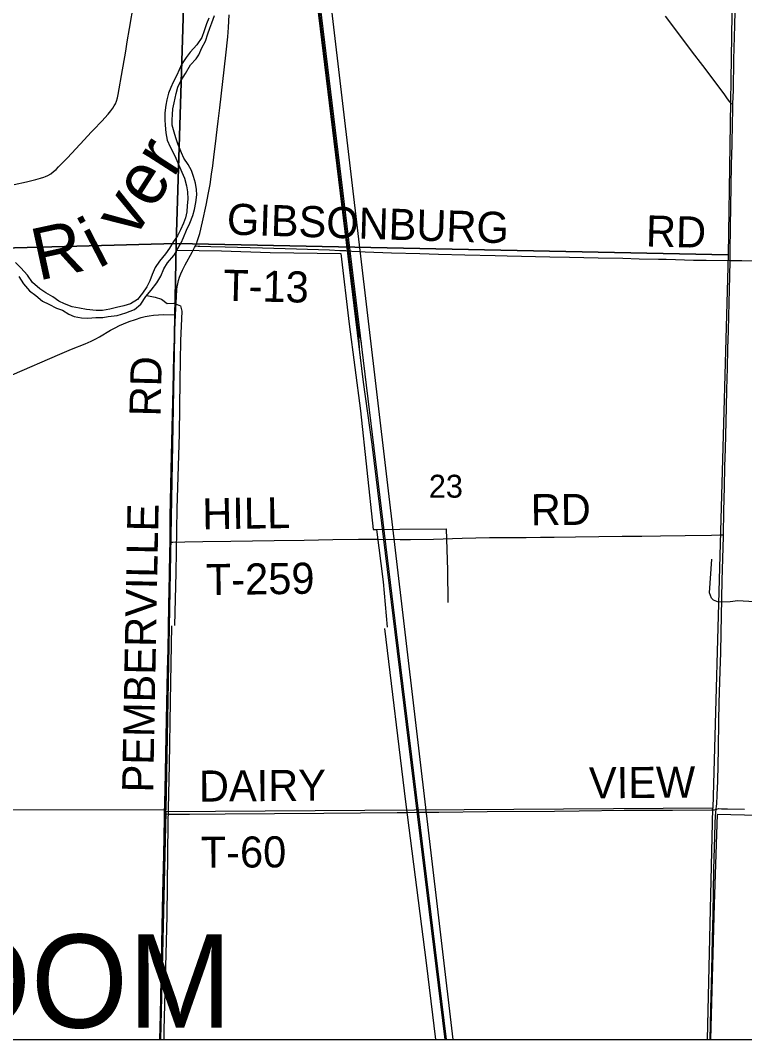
# Model space of a CAD drawing. Extents: x 0 to 34, y 0 to 22.
# Drawn here: x 4.754 to 6.077, y 14.1 to 15.963 of the extents above; entities that cross this region are included whole.
import ezdxf

# ---------------------------------------------------------------- set-up
doc = ezdxf.new("R2010")
doc.units = 0
for name, color, linetype in [('Default', 7, 'Continuous'), ('GM_X_County_Road', 7, 'Continuous'), ('GM_X_County_Road_Text', 7, 'Continuous'), ('GM_X_Major_River', 7, 'Continuous'), ('GM_X_Major_River_Text', 7, 'Continuous'), ('GM_X_Minor_River', 7, 'Continuous'), ('GM_X_Rail_Line', 7, 'Continuous'), ('GM_X_Section', 7, 'Continuous'), ('GM_X_Section_Text', 7, 'Continuous'), ('GM_X_Township_Road', 7, 'Continuous'), ('GM_X_Township_Road_Text', 7, 'Continuous'), ('GM_X_Township_Text', 7, 'Continuous'), ('SH_Cut_Line', 7, 'Continuous'), ('SH_Data', 7, 'Continuous')]:
    doc.layers.add(name, color=color, linetype=linetype)

msp = doc.modelspace()

# ---------------------------------------------------------------- linework, layer by layer
at = {"layer": 'Default'}
for points in [[(4.0075, 14.1), (5.0106, 14.1), (5.0199, 14.516), (5.0199, 14.5201), (4.0206, 14.5179)], [(5.0106, 14.1), (6.0095, 14.1), (6.0193, 14.5231), (5.0199, 14.516)]]:
    msp.add_lwpolyline(points, close=True, dxfattribs=at)
msp.add_lwpolyline([(2.1, 14.1), (7.0155, 14.1)], dxfattribs=at)
at = {"layer": 'GM_X_County_Road'}
for points in [[(4.7429, 15.663), (4.7657, 15.668), (4.7823, 15.6718), (4.7914, 15.6742), (4.7974, 15.6761), (4.8003, 15.6773), (4.8046, 15.6793), (4.81, 15.6826), (4.815, 15.6864), (4.8198, 15.6905), (4.8242, 15.6949), (4.8285, 15.6994), (4.8402, 15.7119), (4.871, 15.7448), (4.8839, 15.7583), (4.8882, 15.7628), (4.9031, 15.7787), (4.9147, 15.7913), (4.9197, 15.7973), (4.9234, 15.8024), (4.9259, 15.8064), (4.928, 15.8106), (4.9298, 15.815), (4.9317, 15.821), (4.9331, 15.8271), (4.9349, 15.8379), (4.939, 15.8624), (4.9468, 15.9068), (4.9497, 15.9237), (4.9539, 15.9482), (4.9617, 15.9942)], [(5.0741, 15.5507), (5.0758, 15.5545), (5.078, 15.5603), (5.0799, 15.5662), (5.0819, 15.5736), (5.0869, 15.5947), (5.0936, 15.6251), (5.0982, 15.6479), (5.101, 15.6632), (5.1038, 15.6816), (5.1059, 15.6969), (5.1085, 15.7185), (5.1108, 15.737), (5.1138, 15.7632), (5.1156, 15.7787), (5.1186, 15.8033), (5.1243, 15.8512), (5.1298, 15.899), (5.1333, 15.933), (5.1346, 15.95), (5.1359, 15.9732)], [(5.038, 15.4248), (5.0396, 15.4581), (5.0404, 15.4705), (5.041, 15.4768), (5.0417, 15.4814), (5.0431, 15.4875), (5.045, 15.4935), (5.0473, 15.4994), (5.0505, 15.5065), (5.0556, 15.5162), (5.0684, 15.5393), (5.0726, 15.5475), (5.0741, 15.5507)], [(5.0277, 15.0091), (5.0283, 15.056), (5.0301, 15.1411), (5.0319, 15.2188), (5.0334, 15.2897), (5.0348, 15.3506), (5.0366, 15.3964), (5.038, 15.4248)], [(5.0176, 14.5124), (5.0186, 14.5562), (5.0208, 14.6538), (5.022, 14.7147), (5.0234, 14.7744), (5.0243, 14.813), (5.0258, 14.8937), (5.0268, 14.9503), (5.0274, 14.9907), (5.0277, 15.0091)], [(5.0092, 14.1), (5.0102, 14.1454), (5.0134, 14.307), (5.0145, 14.3673), (5.0162, 14.4381), (5.0174, 14.5034), (5.0176, 14.5124)]]:
    msp.add_lwpolyline(points, dxfattribs=at)
at = {"layer": 'GM_X_Major_River'}
for points in [[(5.0985, 15.967), (5.0941, 15.9565), (5.09, 15.9437), (5.0859, 15.9313), (5.0765, 15.9182), (5.0648, 15.9045), (5.0573, 15.8948), (5.0487, 15.8825), (5.0443, 15.8723), (5.0399, 15.8626), (5.0335, 15.8502), (5.0291, 15.8401), (5.0251, 15.8299), (5.0221, 15.8178), (5.02, 15.808), (5.0185, 15.794), (5.0185, 15.7811), (5.0191, 15.7716), (5.0202, 15.7572), (5.0225, 15.7442), (5.0283, 15.7319), (5.0333, 15.7216), (5.0384, 15.7108), (5.0491, 15.6854), (5.054, 15.6743), (5.058, 15.6605), (5.0597, 15.6494), (5.0604, 15.6363), (5.059, 15.6245), (5.0583, 15.6132), (5.0561, 15.6022), (5.0525, 15.5924), (5.0469, 15.58), (5.0413, 15.5692), (5.0339, 15.5587), (5.0267, 15.5468), (5.0197, 15.5359), (5.0083, 15.5225), (5.0003, 15.5112), (4.9949, 15.4986), (4.9908, 15.4869), (4.9852, 15.476), (4.9777, 15.4644), (4.9684, 15.4525), (4.9553, 15.4445), (4.9431, 15.441), (4.9298, 15.4379), (4.9179, 15.4348), (4.9046, 15.4328), (4.8929, 15.4323), (4.8751, 15.4343), (4.8623, 15.4369), (4.8491, 15.4391), (4.8347, 15.4446), (4.8249, 15.4497), (4.8138, 15.4576), (4.8009, 15.4646), (4.7898, 15.4721), (4.7768, 15.4837), (4.7672, 15.4969), (4.7551, 15.5104), (4.7455, 15.5205)], [(4.7513, 15.4946), (4.76, 15.4815), (4.7711, 15.4687), (4.7826, 15.4601), (4.7945, 15.4499), (4.8065, 15.4443), (4.8203, 15.4368), (4.8312, 15.4331), (4.8431, 15.4256), (4.8529, 15.4219), (4.866, 15.4193), (4.8778, 15.4187), (4.8922, 15.4195), (4.9047, 15.4199), (4.915, 15.4216), (4.931, 15.4235), (4.947, 15.4284), (4.9626, 15.4346), (4.9746, 15.4444), (4.9836, 15.4579), (4.9934, 15.4698), (5.0036, 15.4832), (5.0111, 15.4955), (5.0167, 15.509), (5.0234, 15.5195), (5.0344, 15.5329), (5.0399, 15.543), (5.0478, 15.5561), (5.0526, 15.5659), (5.0578, 15.5794), (5.0639, 15.5925), (5.0695, 15.6061), (5.0724, 15.6174), (5.075, 15.6298), (5.0765, 15.6442), (5.076, 15.6537), (5.0744, 15.6655), (5.0709, 15.6778), (5.067, 15.6885), (5.0608, 15.6996), (5.0532, 15.7108), (5.0485, 15.7208), (5.0421, 15.7373), (5.0382, 15.7484), (5.035, 15.7583), (5.0319, 15.7713), (5.0314, 15.7812), (5.032, 15.791), (5.033, 15.8009), (5.0352, 15.8122), (5.0387, 15.8292), (5.042, 15.8409), (5.0472, 15.8522), (5.0562, 15.8656), (5.0654, 15.8817), (5.0752, 15.8923), (5.0802, 15.8999), (5.0858, 15.9127), (5.0925, 15.9251), (5.097, 15.9382), (5.1007, 15.9488), (5.104, 15.9586), (5.1092, 15.9717)]]:
    msp.add_lwpolyline(points, dxfattribs=at)
at = {"layer": 'GM_X_Minor_River'}
for points in [[(5.0399, 15.543), (5.122, 15.5414), (5.2106, 15.5389), (5.34, 15.5365), (5.3547, 15.4079), (5.3757, 15.2491), (5.3874, 15.141), (5.3987, 15.0322), (5.4052, 15.0321), (5.4476, 15.0329), (5.5324, 15.0335), (5.5344, 14.958), (5.5352, 14.8987)], [(4.9855, 15.4601), (5.0003, 15.4567), (5.0119, 15.4534), (5.0223, 15.4452), (5.0345, 15.446), (5.0469, 15.441), (5.0496, 15.4316)], [(5.0496, 15.4316), (5.0468, 15.3774), (5.0457, 15.3038), (5.0445, 15.2074), (5.0403, 15.0701), (5.0385, 14.9533), (5.0361, 14.8566)], [(5.4052, 15.0321), (5.4168, 14.9365), (5.4246, 14.8536)], [(6.1645, 14.8956), (6.065, 14.9022), (6.051, 14.9002), (6.0298, 14.8996), (6.0204, 14.9029), (6.0167, 14.9068), (6.0131, 14.9163), (6.0173, 14.9781)], [(5.0302, 14.8562), (5.0281, 14.718), (5.0263, 14.6022), (5.024, 14.4955), (5.0221, 14.3257), (5.0165, 14.1181), (5.0162, 14.1)], [(5.4196, 14.8514), (5.4579, 14.5345), (5.4954, 14.2401), (5.5126, 14.1)], [(6.3168, 14.5272), (6.3166, 14.5075), (6.1764, 14.5075), (6.0272, 14.5114), (6.0217, 14.3475), (6.0152, 14.1)]]:
    msp.add_lwpolyline(points, dxfattribs=at)
at = {"layer": 'GM_X_Rail_Line'}
for p, q in [((5.3745, 15.3541), (5.3721, 15.3935)), ((5.3721, 15.3935), (5.3771, 15.374)), ((5.4556, 14.8553), (5.5444, 14.1))]:
    msp.add_line(p, q, dxfattribs=at)
for points in [[(5.533, 14.1), (5.4414, 14.8452), (5.2368, 16.5291), (5.1973, 16.873), (5.1794, 17.0253), (5.1537, 17.2322), (5.1303, 17.4189), (5.1198, 17.5024), (5.1038, 17.6379), (5.0605, 17.8802), (4.9539, 18.5048), (4.7781, 19.5207), (4.6486, 20.2766), (4.541, 20.9)], [(5.1575, 17.231), (5.1689, 17.2254), (5.1772, 17.2171), (5.4556, 14.8553)], [(5.3972, 15.1881), (5.3809, 15.3015), (5.2318, 16.5285), (5.1928, 16.873), (5.1831, 16.9698)], [(5.3721, 15.3935), (5.372, 15.3954), (5.2343, 16.5288), (5.2026, 16.8071)], [(5.5304, 14.1), (5.4389, 14.8449), (5.3972, 15.1881)]]:
    msp.add_lwpolyline(points, dxfattribs=at)
at = {"layer": 'GM_X_Section'}
for points in [[(4.0656, 16.5335), (5.0695, 16.5364), (5.0389, 15.5548), (4.0396, 15.5284)], [(5.0695, 16.5364), (6.0628, 16.5344), (6.0471, 15.5341), (5.0389, 15.5548)], [(5.0389, 15.5548), (5.0199, 14.5201), (4.0206, 14.5179), (4.0396, 15.5284)], [(6.0471, 15.5341), (6.0193, 14.5231), (5.0199, 14.516), (5.0199, 14.5201), (5.0389, 15.5548)]]:
    msp.add_lwpolyline(points, close=True, dxfattribs=at)
at = {"layer": 'GM_X_Township_Road'}
for points in [[(6.056, 15.8095), (6.056, 15.8106), (6.0568, 15.8355), (6.0579, 15.8914), (6.0596, 15.9535), (6.0617, 16.0608), (6.0625, 16.0903), (6.0647, 16.2006), (6.067, 16.3389), (6.0681, 16.426), (6.0688, 16.4679), (6.0691, 16.4959), (6.0695, 16.5301)], [(5.9323, 15.9708), (5.9585, 15.9361), (5.9818, 15.905), (6.0004, 15.8801), (6.0229, 15.8504), (6.0405, 15.8266), (6.0454, 15.8197), (6.0497, 15.814), (6.0527, 15.8112), (6.056, 15.8095)], [(6.0507, 15.524), (6.0511, 15.5402), (6.0518, 15.5853), (6.053, 15.6599), (6.0536, 15.6987), (6.0544, 15.736), (6.0555, 15.7749), (6.0557, 15.7982), (6.056, 15.8095)], [(5.0741, 15.5507), (5.0794, 15.5504), (5.0824, 15.5503), (5.102, 15.5495), (5.1283, 15.5487), (5.1967, 15.5472), (5.2588, 15.5453), (5.3193, 15.5432), (5.338, 15.5425), (5.3489, 15.542), (5.3535, 15.5415), (5.3597, 15.541), (5.3736, 15.5403), (5.3844, 15.5399), (5.4326, 15.5382), (5.4838, 15.5366), (5.518, 15.5357), (5.5661, 15.5341), (5.622, 15.533), (5.6438, 15.5325), (5.7215, 15.5306), (5.7572, 15.5299), (5.81, 15.529), (5.855, 15.528), (5.8846, 15.5273), (5.9203, 15.5265), (5.9342, 15.5262), (5.9513, 15.5257), (5.9839, 15.5249), (6.0072, 15.5246), (6.0507, 15.524)], [(6.0386, 15.0225), (6.0396, 15.0664), (6.0406, 15.1099), (6.0414, 15.1472), (6.0423, 15.1798), (6.0436, 15.2295), (6.0442, 15.2559), (6.0449, 15.2885), (6.046, 15.3274), (6.0469, 15.3631), (6.0479, 15.3957), (6.0485, 15.4222), (6.0501, 15.4952), (6.0507, 15.524)], [(6.0507, 15.524), (6.0724, 15.5237), (6.1066, 15.5232)], [(4.7396, 15.3151), (4.8265, 15.3528), (4.848, 15.3619), (4.8725, 15.3718), (4.8839, 15.3768), (4.8923, 15.3809), (4.8991, 15.3847), (4.9192, 15.3966), (4.9273, 15.4011), (4.9356, 15.4053), (4.9427, 15.4084), (4.9528, 15.4123), (4.9645, 15.4164), (4.9748, 15.4195), (4.9823, 15.4214), (4.9899, 15.4229), (4.9975, 15.424), (5.0068, 15.4247), (5.016, 15.425), (5.038, 15.4248)], [(5.0277, 15.0091), (5.0329, 15.0092), (5.0547, 15.0096), (5.0874, 15.0101), (5.1387, 15.0108), (5.218, 15.012), (5.2725, 15.0129), (5.3254, 15.0139), (5.372, 15.0146), (5.3953, 15.0148), (5.4062, 15.0148), (5.4483, 15.0139), (5.467, 15.014), (5.5089, 15.0149), (5.5617, 15.0164), (5.6114, 15.0175), (5.6533, 15.018), (5.6782, 15.018), (5.7046, 15.0181), (5.7294, 15.0184), (5.7683, 15.0189), (5.8537, 15.0201), (5.8894, 15.0204), (5.9236, 15.0209), (5.9686, 15.0212), (6.0168, 15.0219), (6.0323, 15.0223), (6.0386, 15.0225)], [(6.0255, 14.5209), (6.0263, 14.5273), (6.0267, 14.5304), (6.0275, 14.5474), (6.0282, 14.5722), (6.0294, 14.6313), (6.0306, 14.6826), (6.0312, 14.7152), (6.0327, 14.7743), (6.0337, 14.8069), (6.0344, 14.8442), (6.0349, 14.8737), (6.0365, 14.939), (6.0386, 15.0197), (6.0386, 15.0225)], [(5.0176, 14.5124), (5.0242, 14.5122), (5.0352, 14.5119), (5.0631, 14.5119), (5.1284, 14.5124), (5.2186, 14.5133), (5.3087, 14.5139), (5.4424, 14.5151), (5.4595, 14.5153), (5.4796, 14.5156), (5.4998, 14.5156), (5.5185, 14.5158), (5.607, 14.5167), (5.7298, 14.5178), (5.7749, 14.5183), (5.8573, 14.5191), (5.9459, 14.5195), (6.0167, 14.5202), (6.0222, 14.5201), (6.0255, 14.5209)], [(6.0143, 14.1), (6.0155, 14.156), (6.0173, 14.2259), (6.0186, 14.285), (6.0197, 14.33), (6.0214, 14.4109), (6.0227, 14.4715), (6.0234, 14.4948), (6.0241, 14.5088), (6.0247, 14.515), (6.0255, 14.5209)], [(6.0255, 14.5209), (6.0267, 14.5212), (6.0298, 14.5221), (6.0353, 14.522), (6.0463, 14.5219), (6.0774, 14.5212)]]:
    msp.add_lwpolyline(points, dxfattribs=at)
at = {"layer": 'SH_Cut_Line'}
msp.add_lwpolyline([(2.1, 20.9), (2.1, 14.1), (7.0155, 14.1)], dxfattribs=at)
at = {"layer": 'SH_Data'}
msp.add_line((2.1, 14.1), (8.9, 14.1), dxfattribs=at)

# ---------------------------------------------------------------- texts
at = {"layer": 'GM_X_County_Road_Text'}
for s, height, rotation, p in [('RD', 0.05682, 88.5163, (5.0102, 15.2385)), ('PEMBERVILLE', 0.056818, 88.9073, (4.9969, 14.5512))]:
    msp.add_text(s, height=height, rotation=rotation, dxfattribs=at).set_placement(p)
at = {"layer": 'GM_X_Major_River_Text'}
for s, height, rotation, p in [('ver', 0.09476, 57.2835, (4.9616, 15.561)), ('R', 0.0948, 12.2825, (4.787, 15.4869)), ('i', 0.0948, 27.2833, (4.8966, 15.5086))]:
    msp.add_text(s, height=height, rotation=rotation, dxfattribs=at).set_placement(p)
at = {"layer": 'GM_X_Section_Text'}
msp.add_text('23', height=0.04186, rotation=0, dxfattribs=at).set_placement((5.5005, 15.0905))
at = {"layer": 'GM_X_Township_Road_Text'}
for s, rotation, p in [('GIBSONBURG', 358.2026, (5.131, 15.5715)), ('RD', 358.5235, (5.8966, 15.5498)), ('T-13', 358.6013, (5.1244, 15.4506)), ('HILL', 0.9008, (5.087, 15.0325)), ('RD', 0.482, (5.6869, 15.04)), ('T-259', 0.8392, (5.0936, 14.9122)), ('DAIRY', 0.4338, (5.0807, 14.5349)), ('VIEW', 0.5253, (5.7933, 14.5407)), ('T-60', 0.3535, (5.084, 14.4139))]:
    msp.add_text(s, height=0.05682, rotation=rotation, dxfattribs=at).set_placement(p)
at = {"layer": 'GM_X_Township_Text'}
msp.add_text('FREEDOM', height=0.17045, rotation=0, dxfattribs=at).set_placement((4.0011, 14.1217))

doc.saveas('drawing.dxf')
